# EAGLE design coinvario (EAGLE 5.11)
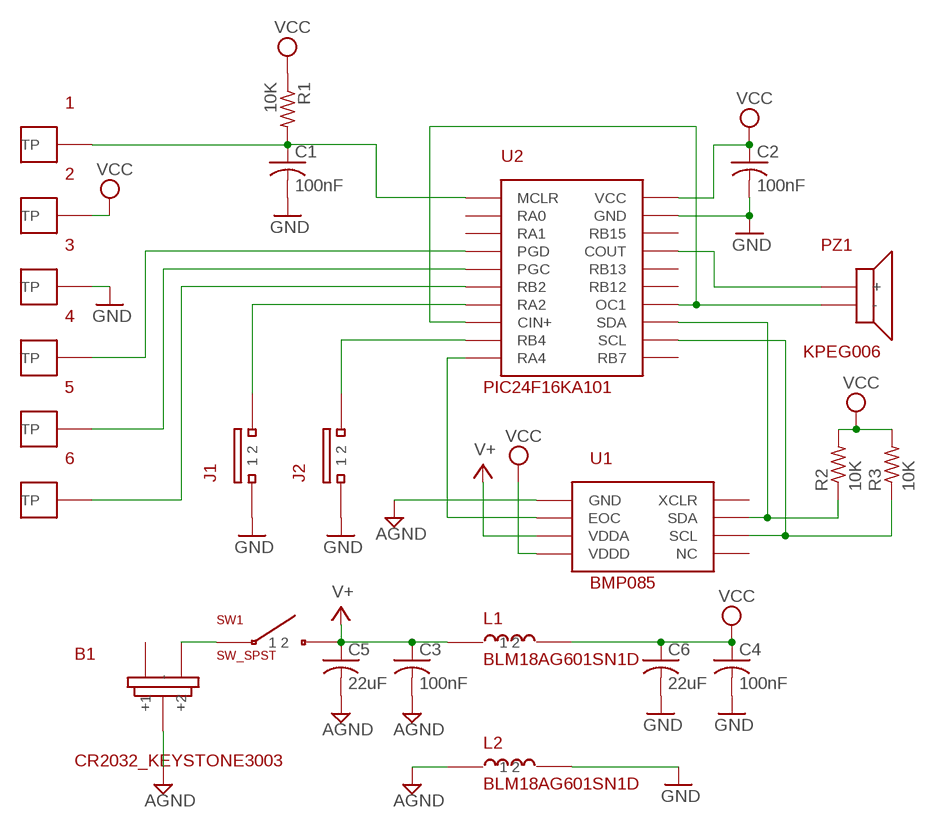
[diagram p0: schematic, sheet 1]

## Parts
1  TEST_PT  [TEST_PT]
2  TEST_PT  [TEST_PT]
3  TEST_PT  [TEST_PT]
4  TEST_PT  [TEST_PT]
5  TEST_PT  [TEST_PT]
6  TEST_PT  [TEST_PT]
B1  CR2032_KEYSTONE3003  [CR2032_KEYSTONE3003]
C1  100nF  C-USC0603  [C0603]
C2  100nF  C-USC0603  [C0603]
C3  100nF  C-USC0603  [C0603]
C4  100nF  C-USC0603  [C0603]
C5  22uF  C-USC1206  [C1206]
C6  22uF  C-USC1206  [C1206]
J1  SOLDER_JUMPER  [SOLDER_JUMPER]
J2  SOLDER_JUMPER  [SOLDER_JUMPER]
L1  BLM18AG601SN1D  FERRITE  [0603]
L2  BLM18AG601SN1D  FERRITE  [0603]
PZ1  KPEG006  PIEZO1  [PIEZO1]
R1  10K  R-US_R0603  [R0603]
R2  10K  R-US_R0603  [R0603]
R3  10K  R-US_R0603  [R0603]
SW1  SW_SPST  [PIEZO1]
U1  BMP085  [BMP085]
U2  PIC24F16KA101  [PIC_SSOP20]

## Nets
AGND: B1.- C3.2 C5.2 L2.1 U1.GND
GND: 3.TP C1.2 C2.2 C4.2 C6.2 J1.1 J2.1 L2.2 U2.GND
N$1: 1.TP C1.1 R1.2 U2.MCLR
N$2: J2.2 U2.RB4
N$3: B1.+2 SW1.+
N$5: R3.1 U1.SCL U2.SCL
N$6: R2.1 U1.SDA U2.SDA
N$7: U1.EOC U2.RA4
N$8: PZ1.- U2.CIN+ U2.OC1
N$9: PZ1.+ U2.COUT
N$10: J1.2 U2.RA2
N$13: 4.TP U2.PGD
N$14: 5.TP U2.PGC
N$15: 6.TP U2.RB2
V+: C3.1 C5.1 L1.1 SW1.- U1.VDDA
VCC: 2.TP C2.1 C4.1 C6.1 L1.2 R1.1 R2.2 R3.2 U1.VDDD U2.VCC
Unconnected: B1.+1 U1.NC U1.XCLR U2.RA0 U2.RA1 U2.RB7 U2.RB12 U2.RB13 U2.RB15

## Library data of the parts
1-6 = mylib:TEST_PT
B1 = mylib:CR2032_KEYSTONE3003
C1-C6 = resistor:C-US: CAPACITOR, American symbol
J1 J2 = mylib:SOLDER_JUMPER
L1 L2 = mylib:FERRITE
PZ1 = mylib:PIEZO1
R1-R3 = resistor:R-US_: RESISTOR, American symbol
SW1 = mylib:SW_SPST
U1 = mylib:BMP085
U2 = mylib:PIC24F16KA101

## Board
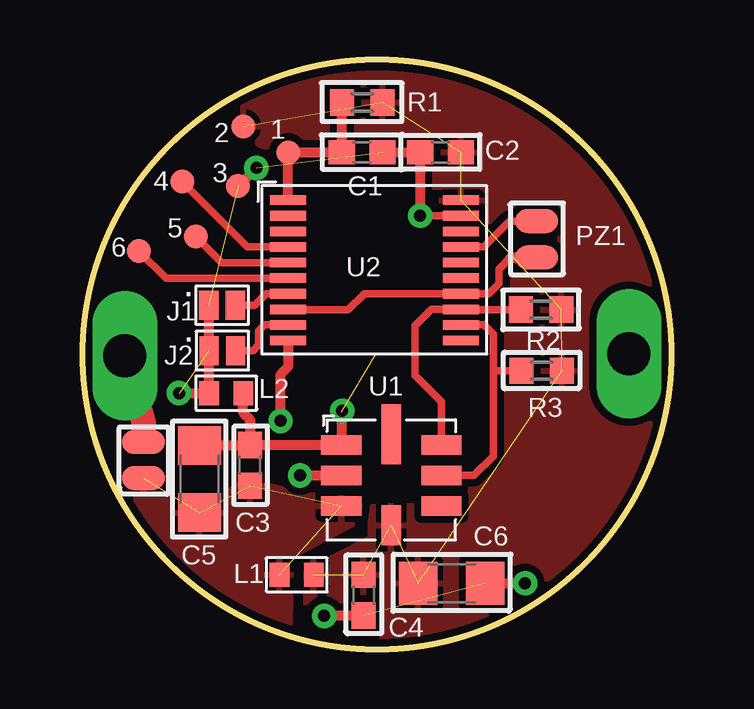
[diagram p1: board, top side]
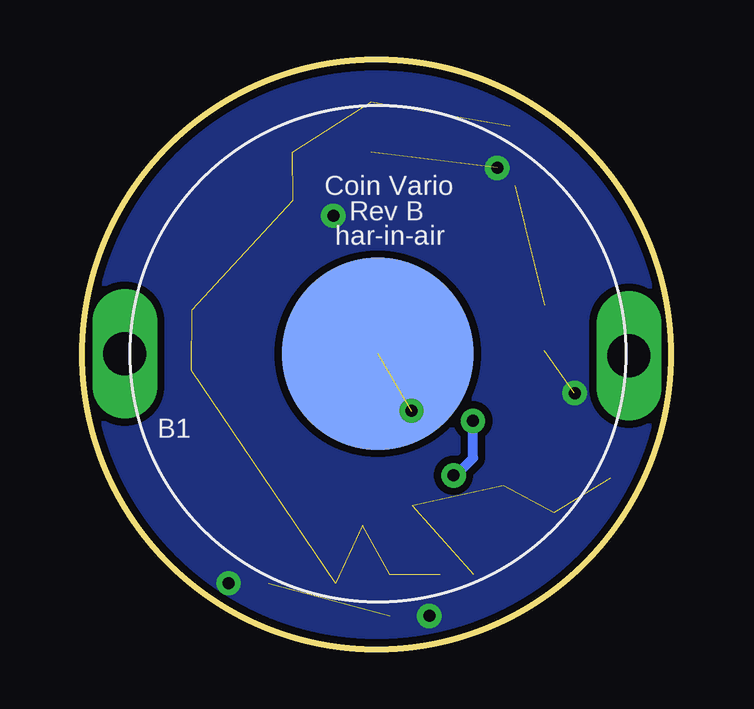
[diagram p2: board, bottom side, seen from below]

Size 24.54 x 24.54 mm. Coordinates in mm from the lower left corner, seen from the top.
Outline: circle at 12.27,12.27 radius 12.27
Copper layers (1*16): Top 0.035mm / dielectric 1.5mm / Bottom 0.035mm
Design rules "SparkFun": minimum track width 8mil, minimum drill 20mil, track to track 8mil, track to pad 8mil, pad to pad 8mil, via to via 8mil, smd to smd 8mil, copper to edge 10mil, drill to drill 8mil, minimum pad ring 12mil, minimum via ring 10mil, stop-mask expansion 4mil, vias tented up to drill 25mil, thermal gap 10mil

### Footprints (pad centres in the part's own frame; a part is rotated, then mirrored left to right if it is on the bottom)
TEST_PT = smd 1 x 1: TP 0,0
CR2032_KEYSTONE3003 = drill 1.8 pad 2.2 long: +1 0,0; +2 21.02,-0.08 | smd 8 x 8: - 10.55,0
C0603 = smd 1.1 x 1: 1 -0.85,0; 2 0.85,0
C1206 = smd 1.6 x 1.8: 1 -1.4,0; 2 1.4,0
SOLDER_JUMPER = smd 0.8 x 1.2: 1 0,0; 2 1.1,0
0603 = smd 0.82 x 1: 1 0,0; 2 1.42,0
PIEZO1 = smd 1.8 x 1: + 0,0; - 0,-1.51
R0603 = smd 1 x 1.1: 1 -0.85,0; 2 0.85,0
BMP085 = smd 1.67 x 0.8: EOC 0,-1.27; GND 0,0; NC 4.17,-2.54; SCL 4.17,-1.27; SDA 4.17,0; VDDA 0,-2.54 | smd 0.8 x 1.67: VDDD 2.08,-3.35 | smd 0.8 x 2.5: XCLR 2.08,0.45
PIC_SSOP20 = smd 1.5 x 0.4: CIN+ 0,-4.55; COUT 7.2,-1.95; GND 7.2,-0.65; MCLR 0,0; OC1 7.2,-3.9; PGC 0,-2.6; PGD 0,-1.95; RA0 0,-0.65; RA1 0,-1.3; RA2 0,-3.9; RA4 0,-5.85; RB2 0,-3.25; RB4 0,-5.2; RB7 7.2,-5.85; RB12 7.2,-3.25; RB13 7.2,-2.6; RB15 7.2,-1.3; SCL 7.2,-5.2; SDA 7.2,-4.55; VCC 7.2,0

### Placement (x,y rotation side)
1  8.57,20.69 0 top
2  6.7,21.77 0 top
3  6.47,19.29 0 top
4  4.16,19.47 0 top
5  4.71,17.18 0 top
6  2.34,16.59 0 top
B1  22.77,12.3 0 bottom
C1  11.65,20.69 0 top
C2  14.92,20.7 180 top
C3  6.98,7.65 90 top
C4  11.71,2.24 270 top
C5  4.87,7.08 90 top
C6  15.38,2.74 0 top
J1  5.26,14.32 0 top
J2  5.27,12.43 0 top
L1  8.21,3.1 0 top
L2  6.69,10.65 180 top
PZ1  18.93,17.83 0 top
R1  11.65,22.77 180 top
R2  19.11,14.14 0 top
R3  19.13,11.59 0 top
SW1  2.53,8.63 0 top
U1  10.78,8.5 0 top
U2  8.56,18.7 0 top

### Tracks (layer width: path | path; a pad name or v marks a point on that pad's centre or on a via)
AGND  (via drill 0.5)  (1 unrouted)
  Top 0.406: L2.1 6.69,9.85 6.99,9.55 6.99,8.71 | 6.99,8.71 C3.2 6.96,8.48 C5.2 | 6.99,8.71 7.2,8.5 U1.GND 10.82,8.5 v10.82,9.92
  Bottom 0.406: v10.82,9.92 10.79,9.92 10.79,9.89
GND  (via drill 0.5 pad 1.02)  (4 unrouted)
  Top 0.305: v14.07,18.05 U2.GND
  Top 0.406: J1.1 J2.1 L2.2 v4.02,10.65 v4.01,10.66 | C1.2 C2.2 v14.07,18.05 | 3.TP 6.49,19.29 v7.24,20.04 | C4.2 v10.08,1.39 v10.07,1.38 | C6.2 v18.44,2.74
  Bottom 0.406: v7.24,20.04 7.22,20.04 | v10.07,1.38 v10.08,1.38 | v18.44,2.74 18.42,2.74 | v4.01,10.66 4.03,10.66
  Bottom 1.016: v14.07,18.05 v14.08,18.05
  pour Bottom (isolate 0.305): 14.37,24.03 17.77,22.95 20.58,20.91 22.55,18.41 23.85,15.38 24.28,12.14 23.79,8.71 22.34,5.78 20.39,3.34 17.49,1.36 14.09,0.37 10.48,0.37 7.05,1.39 4.27,3.21 2.36,5.41 0.97,8.28 0.29,11.61 0.51,14.83 1.65,17.95 3.56,20.57 6.09,22.55 9.18,23.88 11.59,24.31 14.41,24.05
N$1
  Top 0.406: U2.MCLR 1.TP C1.1 R1.2
N$2
  Top 0.305: U2.RB4 7.59,13.51 7.34,13.26 7.34,12.67 7.1,12.43 J2.2
N$3
  Top 1.016: SW1.+ 2.53,9.45 B1.+2
N$5
  Top 0.305: U2.SCL 16.72,13.51 17.12,13.11 17.12,11.59 | 17.12,11.59 17.12,8.04 16.31,7.23 U1.SCL | 17.12,11.59 R3.1
N$6
  Top 0.305: U1.SDA 14.96,10.31 13.86,11.41 13.86,13.46 14.55,14.15 U2.SDA | U2.SDA R2.1
  Top 0.406: U2.SDA
N$7  (via drill 0.5 pad 1.02)
  Top 0.406: v9.06,7.23 U1.EOC | v8.25,9.5 8.25,11.44 8.56,11.75 U2.RA4
  Bottom 0.406: v9.06,7.23 8.97,7.23 8.25,7.95 v8.25,9.5
N$8
  Top 0.305: U2.CIN+ 8.58,14.13 11.07,14.13 11.74,14.8 U2.OC1 16.94,14.8 17.36,15.22 17.36,15.83 17.82,16.29
  Top 0.406: PZ1.- 18.04,16.32 18.01,16.29 17.82,16.29
N$9
  Top 0.305: U2.COUT 16.72,16.75 17.8,17.83 PZ1.+
N$10
  Top 0.305: U2.RA2 7.64,14.8 7.16,14.32 J1.2
N$13
  Top 0.305: 4.16,19.45 6.86,16.75 U2.PGD
  Top 0.406: 4.TP 4.16,19.45
N$14
  Top 0.305: 5.TP 5.78,16.1 U2.PGC
  Top 0.406: 5.TP
N$15
  Top 0.305: 6.TP 3.47,15.45 U2.RB2
  Top 0.406: 6.TP
V+  (4 unrouted)
  pour Top (isolate 0.305): 8.32,1 6.15,1.99 4.21,3.36 2.61,5.13 1.58,6.73 1.6,7.23 3.36,7.18 4.15,6.35 5.64,6.31 6.66,6.94 7.3,6.93 8.56,6.61 10.02,6.34 11.53,6.27 11.49,5.73 11.35,6.23 11.5,5.33 8.66,3.82 8.63,0.84 8.22,1.04
VCC  (9 unrouted)
  pour Top (isolate 0.305): 9.31,3.71 9.31,0.74 12.02,0.25 15.42,0.68 18.72,2.01 21.1,3.92 22.8,6.46 24.1,9.55 24.37,12.91 23.76,16.03 22.4,19.06 19.93,21.65 16.93,23.41 13.84,24.22 10.2,24.09 6.96,23.04 5.94,22.43 6.31,22.02 6.85,21.58 7.4,20.98 8.78,19.34 14.96,19.24 14.92,5.96 12.1,5.94 12,5.32 12,4.62 10.36,3.77 9.34,3.65

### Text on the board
bPlace: Coin Vario | Rev B | har-in-air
